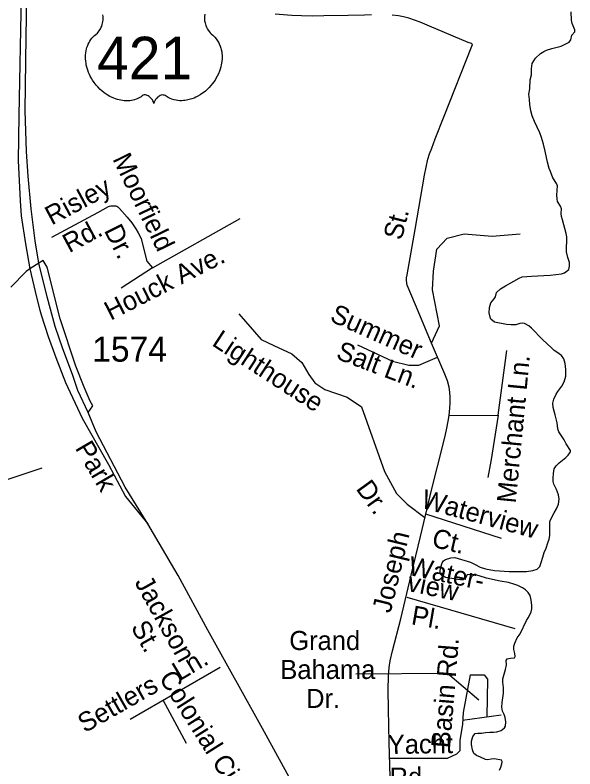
# Model space of a CAD drawing. Extents: x 2290055 to 2389491, y 66597 to 237875.
# Drawn here: x 2333247 to 2336035, y 107689 to 111445 of the extents above; entities that cross this region are included whole.
import ezdxf

# ---------------------------------------------------------------- set-up
doc = ezdxf.new("R2010")
doc.units = 0
for name, color, linetype in [('Exist Hydrographic Island Shore', 7, 'Continuous'), ('Exist Road Non-System Type 51', 7, 'Continuous'), ('Exist Road Non-System Type 51 Label', 7, 'Continuous'), ('Exist Road Primary US Attributed', 7, 'Continuous'), ('Exist Road Primary US Divided Attributed', 7, 'Continuous'), ('Exist Road Primary US Label', 7, 'Continuous'), ('Exist Road Primary US Shield CELL', 7, 'Continuous'), ('Exist Road Primary US Shield Number Label', 7, 'Continuous'), ('Exist Road Secondary Type 51 Attributed', 7, 'Continuous'), ('Exist Road Secondary Type 51 Number Label', 7, 'Continuous')]:
    doc.layers.add(name, color=color, linetype=linetype)

msp = doc.modelspace()

# ---------------------------------------------------------------- linework, layer by layer
at = {"layer": 'Exist Hydrographic Island Shore'}
for points in [[(2335829.7, 111216.5), (2335838.2, 111229.4), (2335864, 111252.5), (2335879.7, 111263.2), (2335893.2, 111270.3), (2335919.7, 111278.5), (2335966.7, 111289.3), (2336006.5, 111309.6), (2336015, 111320.6), (2336019.2, 111344.9), (2336034, 111361.2), (2336034.7, 111371), (2336021.2, 111402.6), (2336018.2, 111419), (2336016, 111461.6)], [(2335616.5, 109929.1), (2335612.7, 109939.3), (2335607.7, 109961.6), (2335608.7, 109987.4), (2335615.5, 110011.7), (2335633.2, 110030.4), (2335639.2, 110041.3), (2335644.5, 110063.1), (2335664.5, 110080.1), (2335689, 110096.1), (2335757, 110134.7), (2335771.7, 110140.5), (2335819, 110144.7), (2335912, 110148.5), (2335967.7, 110155.7), (2335982.2, 110160.1), (2336003.7, 110176.9), (2336008, 110193.2), (2336007.2, 110212.4), (2336000, 110236.4), (2335993, 110265), (2335992.2, 110280.5), (2335994.5, 110324.6), (2335993.7, 110340.1), (2335991.2, 110355.9), (2335972.2, 110424.2), (2335968.7, 110441), (2335966.5, 110456.4), (2335968, 110479.9), (2335962.7, 110492.1), (2335948.5, 110515.7), (2335945.7, 110528.6), (2335945, 110548.1), (2335948, 110594), (2335942.5, 110606.3), (2335925.5, 110633.4), (2335912.5, 110665.8), (2335907.2, 110680.9), (2335898.7, 110711.2), (2335886.2, 110766.8), (2335877.5, 110801.7), (2335868.2, 110834.2), (2335860, 110858), (2335832.7, 110914.2), (2335821.7, 110943.5), (2335815, 110968.2), (2335809.7, 110998.4), (2335808.7, 111024.9), (2335806, 111050.1), (2335811, 111077.3), (2335812, 111121.5), (2335819.2, 111147.7), (2335819.2, 111176.6), (2335822.5, 111203.1), (2335829.7, 111216.5)], [(2335801.7, 108567.7), (2335788, 108580.6), (2335773.5, 108591), (2335750, 108602.4), (2335735, 108608.4), (2335703.7, 108617.6), (2335663.2, 108623.9), (2335594, 108639.2), (2335558, 108651), (2335540, 108655.4), (2335508, 108658.1), (2335498.5, 108655.4), (2335487.5, 108637.1), (2335477.5, 108632), (2335465, 108631.2), (2335449.7, 108632.3), (2335421.2, 108637.3), (2335392.7, 108643.4), (2335371.2, 108653.3), (2335364.2, 108661.5), (2335363.7, 108677.6), (2335367.2, 108694.4), (2335373.5, 108715.8), (2335381, 108725.7), (2335391, 108733.1), (2335416.2, 108741.2), (2335437.5, 108742), (2335514.2, 108718.7), (2335537.5, 108708.1), (2335562.5, 108694.3), (2335590, 108686.7), (2335635, 108678.3), (2335707.5, 108673), (2335778.5, 108672), (2335794, 108673.4), (2335825, 108678), (2335847, 108684.2), (2335859.7, 108698.1), (2335867, 108717.4), (2335874.2, 108744.1), (2335882, 108768.1), (2335891.7, 108789.4), (2335899.7, 108815.3), (2335906.7, 108833.8), (2335909.7, 108852.1), (2335909.5, 108891.1), (2335910.2, 108919.7), (2335913.7, 108929.9), (2335931.5, 108964.6), (2335943.5, 108985.3), (2335952.2, 109008.1), (2335956.5, 109033.7), (2335953.5, 109055.1), (2335943.5, 109080.7), (2335929.5, 109107.3), (2335926.7, 109121), (2335926.5, 109137.5), (2335927.5, 109160.9), (2335932.2, 109183.5), (2335942.2, 109198.7), (2335956, 109214.3), (2335990, 109240.5), (2336001.5, 109252.3), (2336012.5, 109268.4), (2336012.2, 109276.1), (2335990.7, 109308.5), (2335980.5, 109328.2), (2335955, 109368.7), (2335950, 109383.5), (2335946, 109412.6), (2335937, 109453.8), (2335926.2, 109489.2), (2335924.5, 109510.8), (2335929.2, 109531), (2335941, 109555.9), (2335949.2, 109569.2), (2335970, 109596.6), (2335982, 109617.7), (2335989.7, 109645.4), (2335989.5, 109678.5), (2335986, 109708.8), (2335980, 109732.8), (2335967.5, 109749), (2335945.5, 109765.2), (2335931.7, 109773.8), (2335917.5, 109786.6), (2335873.5, 109828.7), (2335818, 109885.7), (2335805.2, 109896.3), (2335783.2, 109908.7), (2335771.7, 109910.1), (2335761, 109908.3), (2335740.2, 109902.2), (2335717.2, 109901.5), (2335694.5, 109903.3), (2335633.5, 109915.2), (2335616.5, 109929.1)], [(2335658.5, 107683.4), (2335665.5, 107697.8), (2335671, 107714.3), (2335672.5, 107725.6), (2335669.5, 107733.4), (2335635, 107739.5), (2335618.5, 107737.7), (2335600.2, 107734.3), (2335589, 107735.4), (2335564.7, 107748), (2335545, 107756.7), (2335531.5, 107765.5), (2335524.5, 107784), (2335520, 107810.8), (2335520.5, 107827.1), (2335527, 107851.5), (2335538, 107865.4), (2335552, 107866.7), (2335569, 107867), (2335589, 107869.9), (2335611.5, 107871.8), (2335630, 107871.8), (2335645.7, 107873.4), (2335666.7, 107880.9), (2335684.7, 107893.4), (2335688.7, 107902.1), (2335690, 107924.4), (2335687.5, 107945.5), (2335682.5, 107960.4), (2335674.5, 107977), (2335670.5, 107996.2), (2335671.7, 108019.4), (2335679.5, 108067.2), (2335679.7, 108094.3), (2335676, 108122), (2335676, 108138.3), (2335681.7, 108161.6), (2335689, 108184.9), (2335693.5, 108208.1), (2335693, 108229.7), (2335697.2, 108236.9), (2335714.7, 108241), (2335733.5, 108243), (2335736.7, 108249.3), (2335735, 108264), (2335730.2, 108284.6), (2335730.5, 108300.7), (2335735, 108316.1), (2335747.5, 108342.4), (2335762, 108361.7), (2335794, 108429.2), (2335802, 108442), (2335810, 108456.9), (2335816.7, 108472), (2335819.5, 108486.6), (2335820.7, 108502.3), (2335819, 108520.5), (2335816, 108537.6), (2335811.2, 108552.9), (2335801.7, 108567.7)]]:
    msp.add_lwpolyline(points, dxfattribs=at)
at = {"layer": 'Exist Road Non-System Type 51'}
for points in [[(2335021.7, 111445.4), (2334987.3, 111444.1), (2334905.6, 111442.2), (2334783.6, 111441), (2334726.2, 111440), (2334673.3, 111441.5), (2334625.6, 111443.3), (2334602.6, 111444.3), (2334541.4, 111448.5)], [(2335195.6, 110125), (2335196.5, 110135.2), (2335199.1, 110150.7), (2335238.8, 110377.1), (2335285.9, 110647.8), (2335303.1, 110726.3), (2335310.9, 110753.8), (2335321.6, 110781.8), (2335338.5, 110828.1), (2335382.9, 110941.1), (2335521.1, 111290.5), (2335525.1, 111298.6), (2335519.3, 111302.6), (2335503, 111308.2), (2335310.4, 111390.2), (2335264, 111410), (2335235.7, 111419.4), (2335207.8, 111429.1), (2335181.9, 111436.3), (2335155.4, 111441.2), (2335124.4, 111444.9)], [(2333429.8, 110339), (2333658.6, 110461.6), (2333712.3, 110490.3), (2333717.8, 110492.8), (2333723.9, 110494.4), (2333735.7, 110495.2), (2333747.9, 110494.4), (2333753.3, 110491.9), (2333758.3, 110488.9), (2333766.5, 110481), (2333805, 110437.2), (2333827.4, 110409.5), (2333847.6, 110380.5), (2333860.2, 110360.6), (2333869.1, 110342.3), (2333874.2, 110330), (2333903.2, 110218.2)], [(2333903.2, 110218.2), (2333931.4, 110185.5), (2334368.3, 110431.6)], [(2335320.9, 109809.9), (2335359.8, 109896.9), (2335325.9, 110075.1), (2335330.1, 110168.5), (2335347.1, 110278.8), (2335398, 110334), (2335482.8, 110355.2), (2335622.8, 110342.5), (2335762.7, 110355.2)], [(2333931.4, 110185.5), (2333774.5, 110083.6)], [(2335116, 107591.3), (2335109.6, 107821.5), (2335105.6, 107987.4), (2335104.9, 108081.2), (2335106, 108153.5), (2335109.6, 108195.3), (2335113.9, 108228), (2335125.7, 108277.7), (2335167, 108436.2), (2335218.8, 108654.5), (2335265, 108847), (2335322.3, 109084), (2335376, 109294.5), (2335390.7, 109355.5), (2335397.3, 109386.6), (2335403.5, 109421), (2335408.6, 109450.7), (2335411.8, 109485.6), (2335414, 109512.9), (2335414.2, 109540.5), (2335412.2, 109566.7), (2335409, 109590.9), (2335400.8, 109622.7), (2335386.4, 109656.6), (2335320.9, 109809.9), (2335240.8, 110001.1), (2335199.9, 110098.9), (2335197.6, 110106.7), (2335195.6, 110125)], [(2334361.5, 109956.3), (2334471.7, 109829), (2334535.4, 109799.2), (2334624.4, 109756.8), (2334675.3, 109714.4), (2334709.2, 109654.9), (2334738.9, 109612.5), (2334789.8, 109578.6), (2334900.1, 109540.4), (2334972.2, 109493.7), (2335086.7, 109171.1), (2335146.1, 109060.8), (2335199.1, 109007.7)], [(2334952.7, 109801.8), (2335126.6, 109721.2), (2335207.1, 109699.9), (2335258, 109699.9), (2335350.3, 109741)], [(2335408.6, 109450.7), (2335652.4, 109451.2), (2335694.9, 109773.8)], [(2335652.4, 109451.2), (2335618.5, 109230.5), (2335601.6, 109141.4)], [(2332807.5, 107769.3), (2333063.7, 109027.7), (2333110.4, 109099.8), (2333381.8, 109189)], [(2335199.1, 109007.7), (2335287.9, 108941.8)], [(2335669.4, 108836.7), (2335291.8, 108957.8)], [(2335737.3, 108386.8), (2335198.7, 108543.9)], [(2333820.3, 107937), (2334268.4, 108196.3)], [(2335512.5, 108157.7), (2335478.6, 107970.9), (2335474.3, 107911.5), (2335461.6, 107830.9), (2335461.6, 107779.9), (2335444.6, 107763), (2335398, 107741.7), (2335111.8, 107741.7)], [(2335512.5, 108157.7), (2335582.9, 108157.7), (2335599.9, 108136.4), (2335595.5, 107948.1)], [(2334100.2, 107816.4), (2333983.5, 108031.4)], [(2335475.7, 107931.4), (2335667.7, 107958.2)]]:
    msp.add_lwpolyline(points, dxfattribs=at)
at = {"layer": 'Exist Road Non-System Type 51 Label'}
msp.add_lwpolyline([(2334944.3, 108162.2), (2335399.7, 108165.7), (2335556.9, 108033.4)], dxfattribs=at)
at = {"layer": 'Exist Road Primary US Attributed'}
msp.add_lwpolyline([(2334725.2, 107441.8), (2334479.4, 107890.6), (2334207.4, 108380.9), (2334058.4, 108653), (2333964.7, 108814.3), (2333907.8, 108909.6)], dxfattribs=at)
at = {"layer": 'Exist Road Primary US Divided Attributed'}
for points in [[(2333301.7, 112222.7), (2333276.8, 111543.4), (2333265.8, 110943.9), (2333262.7, 110720.2), (2333271.7, 110519.6)], [(2333311.2, 110642.8), (2333303.9, 110765.6), (2333296.7, 110968.7), (2333301.6, 111336), (2333313.9, 112056.8), (2333301.7, 112222.7)], [(2333364.6, 110209.1), (2333346.5, 110320.3), (2333327.5, 110479), (2333311.2, 110642.8)], [(2333271.7, 110519.6), (2333276.9, 110445.2), (2333298.8, 110305.3), (2333319.5, 110179.9)], [(2333532.3, 109654), (2333484, 109782.8), (2333446.4, 109894), (2333407.2, 110041.2), (2333364.6, 110209.1)], [(2333319.5, 110179.9), (2333353.2, 110039.6), (2333370, 109975.1)], [(2333370, 109975.1), (2333376.1, 109951.2), (2333411, 109843.3)], [(2333411, 109843.3), (2333449.7, 109738.6), (2333497.9, 109615.1), (2333581.2, 109437.1), (2333711.2, 109205.2), (2333796.9, 109045.6), (2333907.8, 108909.6)], [(2333610.7, 109465.3), (2333559.8, 109573.9), (2333532.3, 109654)], [(2333907.8, 108909.6), (2333795.6, 109092.5), (2333650.9, 109368.8), (2333610.7, 109465.3)]]:
    msp.add_lwpolyline(points, dxfattribs=at)
at = {"layer": 'Exist Road Primary US Shield CELL'}
msp.add_lwpolyline([(2334192, 111449.6), (2334190.5, 111438.1), (2334190.1, 111432.7), (2334190.1, 111427.3), (2334190.4, 111421.6), (2334190.9, 111416.1), (2334191.9, 111410.4), (2334192.8, 111405.4), (2334194.4, 111399.2), (2334196.7, 111392.1), (2334199.5, 111385.2), (2334205.4, 111374), (2334212.9, 111362.6), (2334218.3, 111356.2), (2334223.6, 111350.8), (2334231.6, 111344.1), (2334235.9, 111340.3), (2334240.8, 111335.3), (2334248.9, 111326), (2334252.1, 111321.6), (2334255.4, 111316.6), (2334258.5, 111311.5), (2334261.5, 111306.1), (2334263.9, 111301.3), (2334268.4, 111290.3), (2334271.8, 111279.6), (2334273.3, 111273.9), (2334275.7, 111261.3), (2334276.6, 111255.1), (2334277.6, 111242.8), (2334277.6, 111227.9), (2334276.5, 111213.8), (2334273.8, 111197.3), (2334271.6, 111187.4), (2334268.2, 111175.9), (2334265, 111166), (2334259.1, 111151.3), (2334253.9, 111140.7), (2334247.1, 111128.2), (2334242.5, 111120.7), (2334237.1, 111112.6), (2334230.3, 111103.3), (2334222.4, 111093.5), (2334212.9, 111083.1), (2334205.3, 111075.4), (2334195.2, 111066.4), (2334189.2, 111061.4), (2334180.5, 111054.9), (2334168.7, 111047), (2334157, 111040.2), (2334147, 111035.1), (2334138.2, 111031.3), (2334126.8, 111027), (2334107.8, 111021.7), (2334100.9, 111020.3), (2334092.7, 111019.1), (2334085, 111018.3), (2334077.6, 111017.9), (2334067.6, 111017.9), (2334057.6, 111018.6), (2334048.2, 111020), (2334038.4, 111022), (2334028.2, 111025.1), (2334018.8, 111028.7), (2334009.4, 111033.4), (2333993.5, 111043.4), (2333988.9, 111045.8), (2333986.3, 111046.5), (2333980.2, 111046.8), (2333974.4, 111045.6), (2333968.5, 111043.2), (2333964.9, 111041.3), (2333960.2, 111038.2), (2333956.5, 111035.3), (2333952.1, 111031.2), (2333949.1, 111027.7), (2333946.8, 111024.9), (2333942.3, 111017.9), (2333940.7, 111014.5), (2333939, 111010.2), (2333937.6, 111003.8), (2333935.5, 111011.9), (2333933.2, 111017.2), (2333930.4, 111021.7), (2333927.6, 111025.8), (2333923.1, 111030.9), (2333919.1, 111034.8), (2333914.2, 111038.8), (2333909.1, 111041.9), (2333904.9, 111044), (2333901.1, 111045.4), (2333896.5, 111046.6), (2333892.7, 111046.9), (2333889.6, 111046.8), (2333885.3, 111045.8), (2333879.5, 111041.6), (2333874, 111037.8), (2333868, 111034.1), (2333860.8, 111030.3), (2333855.6, 111027.9), (2333849.4, 111025.5), (2333842.1, 111023), (2333834.2, 111021), (2333826.1, 111019.4), (2333818.9, 111018.2), (2333811.2, 111017.6), (2333804.3, 111017.3), (2333797.1, 111017.4), (2333790.4, 111017.9), (2333782.5, 111018.6), (2333772.8, 111020.1), (2333764.8, 111021.9), (2333756.3, 111024.2), (2333747.5, 111026.9), (2333738.2, 111030.5), (2333726.5, 111035.6), (2333718.4, 111039.7), (2333705.5, 111047.1), (2333690.5, 111057.5), (2333679.1, 111066.7), (2333670.8, 111074.2), (2333658.6, 111086.7), (2333651.4, 111094.8), (2333640.1, 111109.4), (2333632.9, 111120), (2333628.3, 111127.7), (2333621.4, 111140.2), (2333617.7, 111148), (2333612.8, 111159.4), (2333609, 111169.8), (2333605.8, 111179.7), (2333604.1, 111186), (2333601.6, 111197), (2333600.2, 111204.9), (2333598.7, 111215.6), (2333597.9, 111226.9), (2333597.8, 111237.3), (2333598, 111246), (2333599, 111256.1), (2333600.7, 111266.8), (2333602.8, 111276), (2333604.6, 111282.6), (2333607.4, 111290.6), (2333611, 111299.5), (2333615.2, 111308), (2333619.3, 111315.1), (2333624.4, 111322.7), (2333629.4, 111329.2), (2333636, 111336.3), (2333642.8, 111342.9), (2333649.1, 111347.9), (2333656.5, 111355.2), (2333660.4, 111359.6), (2333665.1, 111365.8), (2333668.8, 111371.5), (2333671.7, 111376.6), (2333675.7, 111384.1), (2333678, 111389.7), (2333681, 111398.4), (2333682.5, 111404.5), (2333684, 111412.3), (2333685, 111419.7), (2333685.3, 111428.9), (2333685.1, 111436.5), (2333684.1, 111445.4)], dxfattribs=at)
at = {"layer": 'Exist Road Secondary Type 51 Attributed'}
for points in [[(2333387, 110222.3), (2333364.6, 110209.1)], [(2333610.7, 109465.3), (2333634.4, 109498.1), (2333621.3, 109521), (2333590.3, 109591.4), (2333549.4, 109696.1), (2333470.9, 109931.6), (2333407.2, 110188.4), (2333387, 110222.3)], [(2333364.6, 110209.1), (2333319.5, 110179.9)], [(2333319.5, 110179.9), (2333302.1, 110167.6), (2333226.4, 110089.2)]]:
    msp.add_lwpolyline(points, dxfattribs=at)

# ---------------------------------------------------------------- texts
at = {"layer": 'Exist Road Non-System Type 51 Label'}
for s, rotation, p in [('Moorfield', 295.9432, (2333730.3, 110728)), ('Risley ', 28.1844, (2333428.8, 110395.7)), ('St.', 75.6843, (2335171.4, 110319.1)), ('Rd.', 28.1844, (2333516.3, 110257.7)), ('Dr.', 296.7805, (2333687.8, 110372)), ('Houck Ave.', 27.1214, (2333722.8, 109921.5)), ('Summer', 336.032, (2334809.6, 109921.8)), ('Lighthouse', 326.9529, (2334222.1, 109801.9)), ('Salt Ln.', 339.208, (2334840.2, 109734.4)), ('Merchant Ln.', 84.5184, (2335740.1, 109010.2)), ('Dr.', 305.8785, (2334941, 109084.9)), ('Waterview ', 344.7649, (2335263.6, 108991.6)), ('Ct.', 346.5263, (2335316.9, 108797.3)), ('Joseph', 76.4971, (2335116.6, 108462)), ('Water-', 348.2429, (2335199.8, 108656.7)), ('view', 348.2429, (2335194.8, 108577)), ('Jackson ', 299.1545, (2333839.6, 108618.7)), ('Pl.', 350.1808, (2335215.7, 108410.3)), ('St.', 299.1545, (2333821.2, 108396)), ('Basin Rd.', 85.354, (2335412.7, 107790.4)), ('Ln.', 30.7218, (2334066, 108125.5)), ('Colonial Cir.', 302.2561, (2333960.5, 108142.6)), ('Settlers', 29.6256, (2333593.6, 107866.8)), ('Yacht', 0.841, (2335103.3, 107763.5)), ('Rd.', 0.841, (2335112.7, 107600.1))]:
    msp.add_text(s, height=95, rotation=rotation, dxfattribs=at).set_placement(p)
for s, p in [('   Grand ', (2334506.3, 108281.5)), ('   Bahama', (2334461.7, 108137.3)), ('Dr.', (2334696, 107993.1))]:
    msp.add_text(s, height=95, dxfattribs=at).set_placement(p)
at = {"layer": 'Exist Road Primary US Label'}
msp.add_text('Park', height=95, rotation=300.3569, dxfattribs=at).set_placement((2333543.4, 109288))
at = {"layer": 'Exist Road Primary US Shield Number Label'}
msp.add_text('421', height=212.5, dxfattribs=at).set_placement((2333654.9, 111124.2))
at = {"layer": 'Exist Road Secondary Type 51 Number Label'}
msp.add_text('1574', height=125, dxfattribs=at).set_placement((2333630.9, 109718))

doc.saveas('drawing.dxf')
